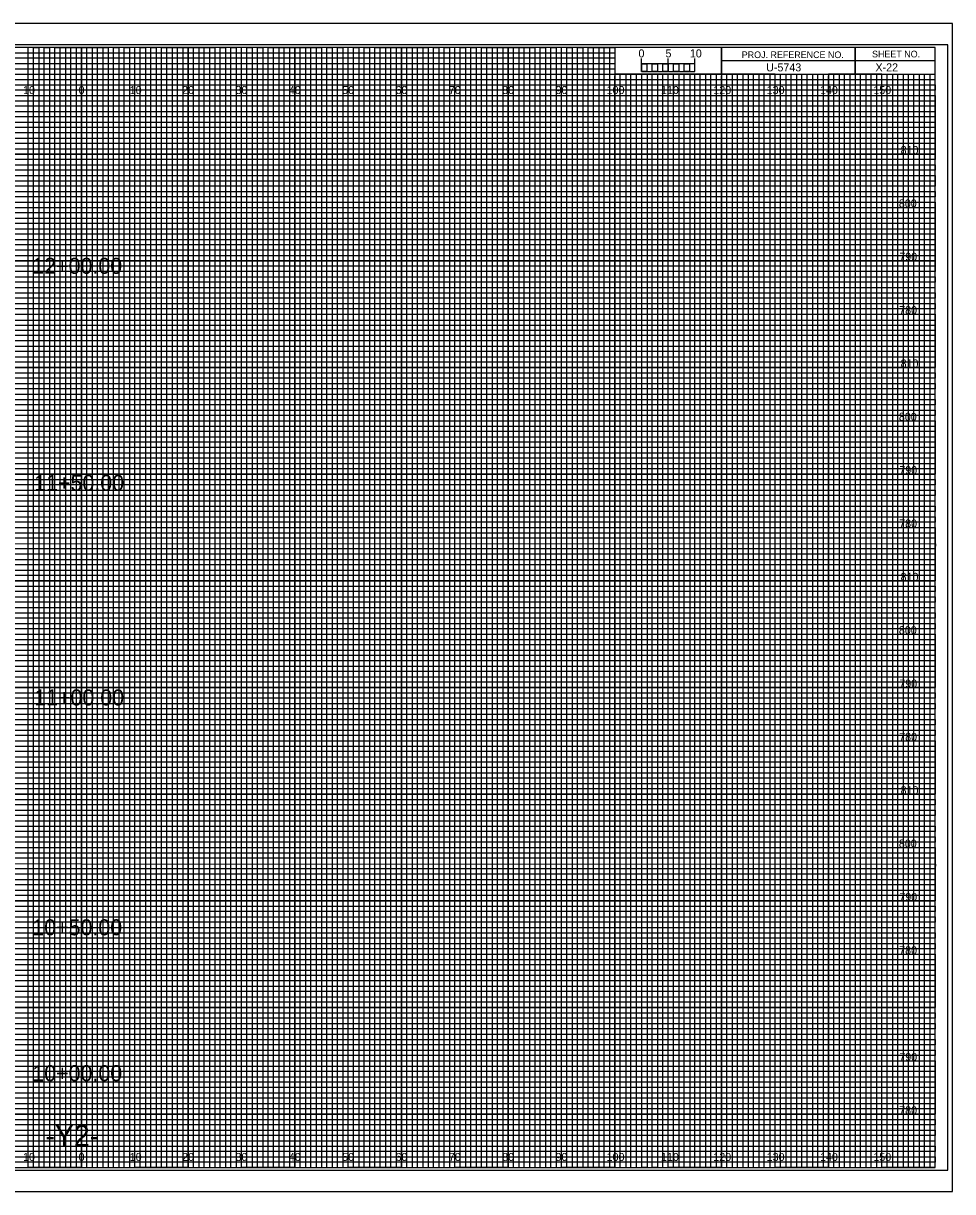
# Model space of a CAD drawing. Extents: x -13 to 323, y -4 to 214.
# Drawn here: x 149.1 to 323.3, y -4.5 to 214.5 of the extents above; entities that cross this region are included whole.
import ezdxf

# ---------------------------------------------------------------- set-up
doc = ezdxf.new("R2010")
doc.units = 0
for name, color, linetype in [('Exist Cross Section Cell', 7, 'Continuous'), ('Exist XS Center Line Elevation Label', 7, 'Continuous'), ('Exist XS Ground Line', 7, 'Continuous'), ('Prop CMT Conc Surface', 7, 'Continuous'), ('Prop CMT Concrete Structures', 7, 'Continuous'), ('Prop CMT Pvmt Course 1', 7, 'Continuous'), ('Prop CMT Pvmt Course 1 CG', 7, 'Continuous'), ('Prop CMT Pvmt Course 2', 7, 'Continuous'), ('Prop CMT Pvmt Course 3', 7, 'Continuous'), ('Prop CMT Pvmt Surface', 7, 'Continuous'), ('Prop CMT Shld Paved Course 1', 7, 'Continuous'), ('Prop CMT Shld Paved Course 2', 7, 'Continuous'), ('Prop CMT Slope Grass', 7, 'Continuous'), ('Prop CMT Subgrade Earthwork', 7, 'Continuous'), ('Prop SS Fill Line', 7, 'Continuous'), ('Prop XS Shear Point Element', 7, 'Continuous'), ('Scratch_Level_4', 7, 'Continuous')]:
    doc.layers.add(name, color=color, linetype=linetype)

msp = doc.modelspace()

# ---------------------------------------------------------------- linework, layer by layer
at = {"layer": 'Exist XS Center Line Elevation Label'}
for points in [[(145, 0), (155, 0), (155, 210), (165, 210), (165, 0), (175, 0), (175, 210), (185, 210), (185, 0), (195, 0), (195, 210), (205, 210), (205, 0), (215, 0), (215, 210), (225, 210), (225, 0), (235, 0), (235, 210), (245, 210), (245, 0), (255, 0), (255, 210), (259.93, 210), (260, 210), (260, 205), (264.99, 205), (264.99, 0), (275, 0), (275, 205), (285, 205), (285, 0), (295, 0), (295, 205), (305, 205), (305, 0), (315, 0), (315, 205)], [(0, 205), (275, 205)], [(0, 185), (320, 185), (320, 195), (0, 195)], [(0, 165), (320, 165), (320, 175), (0, 175)], [(0, 145), (320, 145), (320, 155), (0, 155)], [(0, 125), (320, 125), (320, 135), (0, 135)], [(0, 105), (320, 105), (320, 115), (0, 115)], [(0, 85), (320, 85), (320, 95), (0, 95)], [(0, 65), (320, 65), (320, 75), (0, 75)], [(0, 45), (320, 45), (320, 55), (0, 55)], [(0, 25), (320, 25), (320, 35), (0, 35)], [(0, 5), (320, 5), (320, 15), (0, 15)]]:
    msp.add_lwpolyline(points, dxfattribs=at)
at = {"layer": 'Exist XS Ground Line'}
for p, q in [((150, 210), (140, 210)), ((150, 0), (150, 210)), ((170, 210), (160, 210)), ((160, 210), (160, 0)), ((170, 0), (170, 210)), ((190, 210), (180, 210)), ((180, 210), (180, 0)), ((190, 0), (190, 210)), ((210, 210), (200, 210)), ((200, 210), (200, 0)), ((210, 0), (210, 210)), ((230, 210), (220, 210)), ((220, 210), (220, 0)), ((230, 0), (230, 210)), ((250, 210), (240, 210)), ((240, 210), (240, 0)), ((250, 0), (250, 210)), ((260, 210), (260, 0)), ((270, 0), (270, 205)), ((290, 205), (280, 205)), ((280, 205), (280, 0)), ((290, 0), (290, 205)), ((310, 205), (300, 205)), ((300, 205), (300, 0)), ((310, 0), (310, 205)), ((160, 0), (150, 0)), ((180, 0), (170, 0)), ((200, 0), (190, 0)), ((220, 0), (210, 0)), ((240, 0), (230, 0)), ((260, 0), (250, 0)), ((280, 0), (270, 0)), ((300, 0), (290, 0)), ((320, 0), (310, 0)), ((320, 0), (320, 0))]:
    msp.add_line(p, q, dxfattribs=at)
for points in [[(0, 200), (320, 200), (320, 190), (0, 190)], [(0, 180), (320, 180), (320, 170), (0, 170)], [(0, 160), (320, 160), (320, 150), (0, 150)], [(0, 140), (320, 140), (320, 130), (0, 130)], [(0, 120), (320, 120), (320, 110), (0, 110)], [(0, 100), (320, 100), (320, 90), (0, 90)], [(0, 80), (320, 80), (320, 70), (0, 70)], [(0, 60), (320, 60), (320, 50), (0, 50)], [(0, 40), (320, 40), (320, 30), (0, 30)], [(0, 20), (320, 20), (320, 10), (0, 10)]]:
    msp.add_lwpolyline(points, dxfattribs=at)
at = {"layer": 'Prop CMT Conc Surface'}
for p, q in [((323.3, 214.5), (-13.4, 214.5)), ((-13.4, -4.5), (323.3, -4.5))]:
    msp.add_line(p, q, dxfattribs=at)
at = {"layer": 'Prop CMT Concrete Structures'}
for p, q in [((267, 205), (266.01, 205)), ((266.01, 205), (266.01, 0)), ((267, 0), (267, 205)), ((269, 205), (268, 205)), ((268, 205), (268, 0)), ((269, 0), (269, 205)), ((266.01, 0), (265, 0)), ((268, 0), (267, 0))]:
    msp.add_line(p, q, dxfattribs=at)
for points in [[(150, 0), (151, 0), (151, 210), (152, 210), (152, 0)], [(152, 0), (153, 0), (153, 210), (154, 210), (154, 0)], [(155, 0), (156, 0), (156, 210), (157, 210), (157, 0)], [(157, 0), (158, 0), (158, 210), (159, 210), (159, 0)], [(160, 0), (161, 0), (161, 210), (162, 210), (162, 0)], [(162, 0), (163, 0), (163, 210), (164, 210), (164, 0)], [(165, 0), (166, 0), (166, 210), (167, 210), (167, 0)], [(167, 0), (168, 0), (168, 210), (169, 210), (169, 0)], [(170, 0), (171, 0), (171, 210), (172, 210), (172, 0)], [(172, 0), (173, 0), (173, 210), (174, 210), (174, 0)], [(175, 0), (176, 0), (176, 210), (177, 210), (177, 0)], [(177, 0), (178, 0), (178, 210), (179, 210), (179, 0)], [(180, 0), (181, 0), (181, 210), (182, 210), (182, 0)], [(182, 0), (183, 0), (183, 210), (184, 210), (184, 0)], [(185, 0), (186, 0), (186, 210), (187, 210), (187, 0)], [(187, 0), (188, 0), (188, 210), (189, 210), (189, 0)], [(190, 0), (191, 0), (191, 210), (192, 210), (192, 0)], [(192, 0), (193, 0), (193, 210), (194, 210), (194, 0)], [(195, 0), (196, 0), (196, 210), (197, 210), (197, 0)], [(197, 0), (198, 0), (198, 210), (199, 210), (199, 0)], [(200, 0), (201, 0), (201, 210), (202, 210), (202, 0)], [(202, 0), (203, 0), (203, 210), (204, 210), (204, 0)], [(205, 0), (206, 0), (206, 210), (207, 210), (207, 0)], [(207, 0), (208, 0), (208, 210), (209, 210), (209, 0)], [(210, 0), (211, 0), (211, 210), (212, 210), (212, 0)], [(212, 0), (213, 0), (213, 210), (214, 210), (214, 0)], [(215, 0), (216, 0), (216, 210), (217, 210), (217, 0)], [(217, 0), (218, 0), (218, 210), (219, 210), (219, 0)], [(220, 0), (221, 0), (221, 210), (222, 210), (222, 0)], [(222, 0), (223, 0), (223, 210), (224, 210), (224, 0)], [(225, 0), (226, 0), (226, 210), (227, 210), (227, 0)], [(227, 0), (228, 0), (228, 210), (229, 210), (229, 0)], [(230, 0), (231, 0), (231, 210), (232, 210), (232, 0)], [(232, 0), (233, 0), (233, 210), (234, 210), (234, 0)], [(235, 0), (236, 0), (236, 210), (237, 210), (237, 0)], [(237, 0), (238, 0), (238, 210), (239, 210), (239, 0)], [(240, 0), (241, 0), (241, 210), (242, 210), (242, 0)], [(242, 0), (243, 0), (243, 210), (244, 210), (244, 0)], [(245, 0), (246, 0), (246, 210), (247, 210), (247, 0)], [(247, 0), (248, 0), (248, 210), (249, 210), (249, 0)], [(250, 0), (251, 0), (251, 210), (252, 210), (252, 0)], [(252, 0), (253, 0), (253, 210), (254, 210), (254, 0)], [(255, 0), (256, 0), (256, 210), (257, 210), (257, 0)], [(257, 0), (258, 0), (258, 210), (259, 210), (259, 0)], [(260, 0), (261, 0), (261, 205), (262.02, 205), (262.02, 0)], [(262, 0), (263, 0), (263, 205), (263.99, 205), (263.99, 0)], [(270, 0), (270.98, 0), (270.98, 205), (272, 205), (272, 0)], [(272, 0), (273, 0), (273, 205), (274.05, 205), (274.05, 0)], [(275, 0), (276, 0), (276, 205), (277, 205), (277, 0)], [(277, 0), (278, 0), (278, 205), (279, 205), (279, 0)], [(280, 0), (281, 0), (281, 205), (282, 205), (282, 0)], [(282, 0), (283, 0), (283, 205), (284, 205), (284, 0)], [(285, 0), (286, 0), (286, 205), (287, 205), (287, 0)], [(287, 0), (288, 0), (288, 205), (289, 205), (289, 0)], [(290, 0), (291, 0), (291, 205), (292, 205), (292, 0)], [(292, 0), (293, 0), (293, 205), (294, 205), (294, 0)], [(295, 0), (296, 0), (296, 205), (297, 205), (297, 0)], [(297, 0), (298, 0), (298, 205), (299, 205), (299, 0)], [(300, 0), (301, 0), (301, 205), (302, 205), (302, 0)], [(302, 0), (303, 0), (303, 205), (304, 205), (304, 0)], [(305, 0), (306, 0), (306, 205), (307, 205), (307, 0)], [(307, 0), (308, 0), (308, 205), (309, 205), (309, 0)], [(310, 0), (311, 0), (311, 205), (312, 205), (312, 0)], [(312, 0), (313, 0), (313, 205), (314, 205), (314, 0)], [(315, 0), (316, 0), (316, 205), (317, 205), (317, 0)], [(317, 0), (318, 0), (318, 205), (319, 205), (319, 0)]]:
    msp.add_lwpolyline(points, dxfattribs=at)
at = {"layer": 'Prop CMT Pvmt Course 1'}
msp.add_lwpolyline([(-10.8, -0.5), (322.4, -0.5), (322.4, 210.5), (-10.8, 210.5)], close=True, dxfattribs=at)
at = {"layer": 'Prop CMT Pvmt Course 1 CG'}
msp.add_lwpolyline([(-13.4, -4.5), (323.3, -4.5), (323.3, 214.5), (-13.4, 214.5)], close=True, dxfattribs=at)
at = {"layer": 'Prop CMT Pvmt Course 2'}
for p, q in [((0, 209), (260, 209)), ((260, 209), (260, 207.98)), ((260, 207.98), (0, 207.98)), ((0, 207), (260, 207)), ((260, 205.89), (0, 205.89)), ((260, 207), (260, 205.89)), ((0, 204), (320, 204))]:
    msp.add_line(p, q, dxfattribs=at)
for points in [[(0, 203), (270, 203), (320, 203), (320, 202), (0, 202)], [(0, 201), (320, 201), (320, 199), (0, 199)], [(0, 198), (320, 198), (320, 197), (0, 196.98)], [(0, 196), (320, 196), (320, 194), (0, 194)], [(0, 193), (320, 193), (320, 192), (0, 192)], [(0, 191), (320, 191), (320, 189), (0, 189)], [(0, 188), (320, 188), (320, 187), (0, 187)], [(0, 186), (320, 186), (320, 184), (0, 184)], [(0, 183), (320, 183), (320, 182), (0, 182)], [(0, 181), (320, 181), (320, 179), (0, 179)], [(0, 178), (320, 178), (320, 177), (0, 177)], [(0, 176), (320, 176), (320, 173.95), (320, 173), (320, 172), (0, 172)], [(0, 174), (320, 174), (320, 173), (0, 173)], [(0, 171), (320, 171), (320, 169), (0, 169.03)], [(0, 169.03), (320, 169), (320, 168), (0, 168)], [(0, 167), (320, 167), (320, 166), (0, 166)], [(0, 164), (320, 164), (320, 163), (0, 163)], [(0, 162), (320, 162), (320, 161), (0, 161)], [(-0.07, 158.89), (320, 158.89), (320, 157.88), (-0.07, 157.88)], [(0, 157), (320, 157), (320, 156), (0, 156)], [(0, 154), (320, 154), (320, 153), (0, 153)], [(0, 152), (320, 152), (320, 151), (0, 151)], [(0, 149), (320, 149), (320, 148), (0, 148)], [(0, 147), (320, 147), (320, 146), (0, 146)], [(0, 144), (320, 144), (320, 143), (0, 143)], [(0, 142), (320, 142), (320, 141), (0, 141)], [(0, 139), (320, 139), (319.99, 137.98), (0, 138)], [(0, 137), (320, 137), (320, 136), (0, 136)], [(0, 134), (320, 134), (320, 133), (0, 133)], [(0, 132), (320, 132), (320, 131), (0, 131)], [(0, 129), (320, 129), (320, 128), (0, 128)], [(0, 127), (320, 127), (320, 126), (0, 126)], [(0, 124), (320, 124), (320, 123), (0, 123)], [(0, 122), (320, 122), (320, 121), (0, 121)], [(0, 119), (320, 119), (320, 118), (0, 118)], [(0, 116.99), (320.07, 116.91), (320, 116), (0, 116)], [(0, 114), (320, 114), (320, 113), (0, 113)], [(0, 112), (320, 112), (320, 111), (0, 111)], [(0, 109), (320, 109), (320, 108), (0, 108)], [(0, 107), (320, 107), (320, 106), (0, 106)], [(0, 104), (320, 104), (320, 103), (0, 103)], [(0, 102), (320, 102), (320, 101), (0, 101)], [(0, 99), (320, 99), (320, 98), (0, 98)], [(0, 97), (320, 97), (320, 96), (0, 96)], [(0, 94), (320, 94), (320, 93), (0, 93)], [(0, 92), (320, 92), (320, 91), (0, 91)], [(0, 89), (320, 89), (320, 88), (0, 88)], [(0, 87), (320, 87), (320, 86), (0, 86)], [(0, 84), (320, 84), (320, 83), (0, 83)], [(0, 82), (320, 82), (320, 81), (0, 81)], [(0, 79), (320, 79), (319.99, 77.98), (0, 78)], [(0, 77), (320, 77), (320, 76), (0, 76)], [(0, 74), (320, 74), (320, 73), (0, 73)], [(0, 72), (320, 72), (320, 71), (0, 71)], [(0, 69), (320, 69), (320, 68), (0, 68)], [(0, 67), (320, 67), (320, 66), (0, 66)], [(0, 64), (320, 64), (320, 63), (0, 63)], [(0, 62), (320, 62), (320, 61), (0, 61)], [(0, 59), (320, 59), (320, 58), (0, 58)], [(0, 56.99), (320.07, 56.91), (320, 56), (0, 56)], [(0, 54), (320, 54), (320, 53), (0, 53)], [(0, 52), (320, 52), (320, 51), (0, 51)], [(0, 49), (320, 49), (320, 48), (0, 48)], [(0, 47), (320, 47), (320, 46), (0, 46)], [(0, 44), (320, 44), (320, 43), (0, 43)], [(0, 42), (320, 42), (320, 41), (0, 41)], [(0, 39), (320, 39), (320, 38), (0, 38)], [(0, 37), (320, 37), (320, 36), (0, 36)], [(0, 34), (320, 34), (320, 33), (0, 33)], [(0, 32), (320, 32), (320, 31), (0, 31)], [(0, 29), (320, 29), (320, 28), (0, 28)], [(0, 27), (320, 27), (320, 26), (0, 26)], [(0, 24), (320, 24), (320, 23), (0, 23)], [(0, 22), (320, 22), (320, 21), (0, 21)], [(0, 19), (320, 19), (320, 18), (0, 18)], [(0, 17), (320, 17), (320, 16), (0, 16)], [(0, 14), (320, 14), (320, 13), (0, 13)], [(0, 12), (320, 12), (320, 11), (0, 11)], [(0, 9), (320, 9), (320, 8), (0, 8)], [(0, 7), (320, 7), (320, 6), (0, 6)], [(0, 4), (320, 4), (320, 3), (0, 3)], [(0, 2), (320, 2), (320, 1), (0, 1)]]:
    msp.add_lwpolyline(points, dxfattribs=at)
at = {"layer": 'Prop CMT Pvmt Course 3'}
for p, q in [((305, 210), (305, 205)), ((305, 205), (305, 210)), ((280, 207.5), (280, 205)), ((320, 207.49), (280, 207.49)), ((280, 205), (320, 205))]:
    msp.add_line(p, q, dxfattribs=at)
for points in [[(320, 210), (0, 210), (0, 0), (320, 0)], [(280, 210), (260, 210), (260, 205.03), (280, 205.03)], [(320, 210), (280, 210), (280, 205), (320, 205)]]:
    msp.add_lwpolyline(points, close=True, dxfattribs=at)
at = {"layer": 'Prop SS Fill Line'}
for p, q in [((265, 205.49), (265, 207.9)), ((265, 206.9), (265, 207.9)), ((270, 205.49), (270, 207.9)), ((275, 205.49), (275, 207.9)), ((275, 206.9), (275, 207.9))]:
    msp.add_line(p, q, dxfattribs=at)
for points in [[(275, 206.9), (265, 206.9), (265, 205.49), (275, 205.49)], [(265, 206.9), (266, 206.9), (266, 205.49), (265, 205.49)], [(267, 206.9), (268, 206.9), (268, 205.49), (267, 205.49)], [(269, 206.9), (270, 206.9), (270, 205.49), (269, 205.49)], [(271, 206.9), (272, 206.9), (272, 205.49), (271, 205.49)], [(273, 206.9), (274, 206.9), (274, 205.49), (273, 205.49)]]:
    msp.add_lwpolyline(points, close=True, dxfattribs=at)
at = {"layer": 'Prop XS Shear Point Element'}
for p, q in [((150, 0), (150, 210)), ((160, 0), (160, 210)), ((170, 0), (170, 210)), ((180, 0), (180, 210)), ((190, 0), (190, 210)), ((200, 0), (200, 210)), ((210, 0), (210, 210)), ((220, 0), (220, 210)), ((230, 0), (230, 210)), ((240, 0), (240, 210)), ((250, 0), (250, 210)), ((260, 0), (260, 204.69)), ((270, 0), (270, 204.69)), ((280, 0), (280, 204.69)), ((290, 0), (290, 204.69)), ((300, 0), (300, 204.69)), ((310, 0), (310, 204.69)), ((0, 200), (320, 200)), ((0, 190), (320, 190)), ((0, 180), (320, 180)), ((0, 170), (320, 170)), ((0, 160), (320, 160)), ((0, 150), (320, 150)), ((0, 140), (320, 140)), ((0, 130), (320, 130)), ((0, 120), (320, 120)), ((0, 110), (320, 110)), ((0, 100), (320, 100)), ((0, 90), (320, 90)), ((0, 80), (320, 80)), ((0, 70), (320, 70)), ((0, 60), (320, 60)), ((0, 50), (320, 50)), ((0, 40), (320, 40)), ((0, 30), (320, 30)), ((0, 20), (320, 20)), ((0, 10), (320, 10))]:
    msp.add_line(p, q, dxfattribs=at)

# ---------------------------------------------------------------- texts
at = {"layer": 'Exist Cross Section Cell'}
for s, p in [('10', (149.04, 201.25)), ('0', (159.45, 201.25)), ('0', (159.45, 201.25)), ('10', (169.04, 201.25)), ('20', (178.86, 201.25)), ('30', (188.86, 201.25)), ('40', (198.86, 201.25)), ('50', (208.86, 201.25)), ('60', (218.86, 201.25)), ('70', (228.86, 201.25)), ('80', (238.86, 201.25)), ('90', (248.86, 201.25)), ('100', (258.44, 201.25)), ('110', (268.62, 201.25)), ('120', (278.44, 201.25)), ('130', (288.44, 201.25)), ('140', (298.44, 201.25)), ('150', (308.44, 201.25)), ('10', (149.04, 1.25)), ('0', (159.45, 1.25)), ('0', (159.45, 1.25)), ('10', (169.04, 1.25)), ('20', (178.86, 1.25)), ('30', (188.86, 1.25)), ('40', (198.86, 1.25)), ('50', (208.86, 1.25)), ('60', (218.86, 1.25)), ('70', (228.86, 1.25)), ('80', (238.86, 1.25)), ('90', (248.86, 1.25)), ('100', (258.44, 1.25)), ('110', (268.62, 1.25)), ('120', (278.44, 1.25)), ('130', (288.44, 1.25)), ('140', (298.44, 1.25)), ('150', (308.44, 1.25))]:
    msp.add_text(s, height=1.5, dxfattribs=at).set_placement(p)
at = {"layer": 'Prop CMT Pvmt Course 3'}
for s, p in [('PROJ. REFERENCE NO.', (283.77, 207.99)), ('SHEET NO.', (308.19, 208.12))]:
    msp.add_text(s, height=1.25, dxfattribs=at).set_placement(p)
at = {"layer": 'Prop CMT Pvmt Surface'}
for s, p in [('810', (313.55, 190)), ('800', (313.22, 180)), ('790', (313.3, 170)), ('780', (313.28, 160)), ('810', (313.55, 150)), ('800', (313.22, 140)), ('790', (313.3, 130)), ('780', (313.28, 120)), ('810', (313.55, 110)), ('800', (313.22, 100)), ('790', (313.3, 90)), ('780', (313.28, 80)), ('810', (313.55, 70)), ('800', (313.22, 60)), ('790', (313.3, 50)), ('780', (313.28, 40)), ('790', (313.3, 20)), ('780', (313.28, 10))]:
    msp.add_text(s, height=1.5, dxfattribs=at).set_placement(p)
at = {"layer": 'Prop CMT Shld Paved Course 1'}
msp.add_text('U-5743', height=1.5, dxfattribs=at).set_placement((288.34, 205.5))
at = {"layer": 'Prop CMT Shld Paved Course 2'}
for s, p in [('5', (269.47, 208.12)), ('10', (274.04, 208.12))]:
    msp.add_text(s, height=1.5, dxfattribs=at).set_placement(p)
at = {"layer": 'Prop CMT Slope Grass'}
msp.add_text('X-22', height=1.5, dxfattribs=at).set_placement((308.83, 205.5))
at = {"layer": 'Prop CMT Subgrade Earthwork'}
for s, p in [('12+00.00', (150.77, 167.55)), ('11+50.00', (151.13, 126.87)), ('11+00.00', (151.13, 86.64)), ('10+50.00', (150.77, 43.55)), ('10+00.00', (150.77, 16.2))]:
    msp.add_text(s, height=3, dxfattribs=at).set_placement(p)
at = {"layer": 'Prop SS Fill Line'}
msp.add_text('0', height=1.5, dxfattribs=at).set_placement((264.41, 208.12))
at = {"layer": 'Scratch_Level_4'}
msp.add_text('-Y2-', height=4, dxfattribs=at).set_placement((153.21, 4))

doc.saveas('drawing.dxf')
